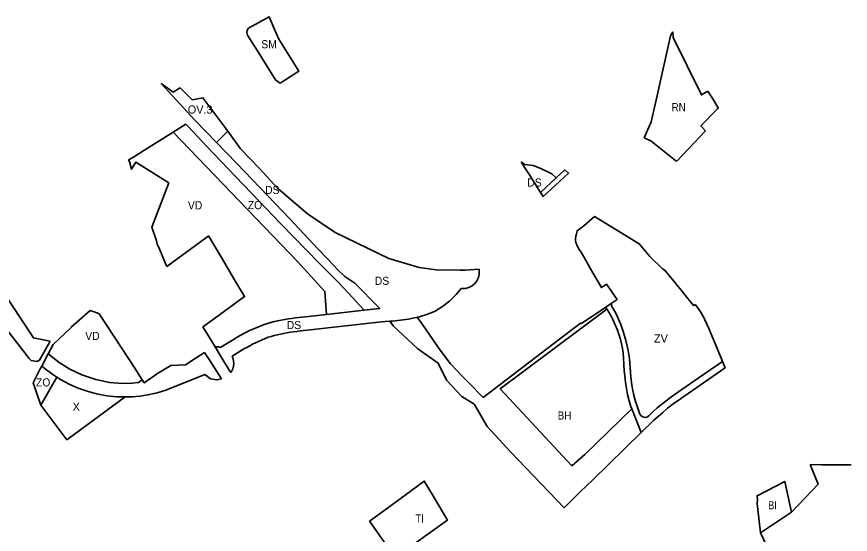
# Model space of a CAD drawing. Extents: x -650971 to -642489, y -1074311 to -1062745.
# Drawn here: x -647426 to -646196, y -1072507 to -1071744 of the extents above; entities that cross this region are included whole.
import ezdxf

# ---------------------------------------------------------------- set-up
doc = ezdxf.new("R2010")
doc.units = 0
doc.header["$LTSCALE"] = 4.8
for name, color, linetype, lineweight in [('1', 7, 'Continuous', 35), ('11', 7, 'Continuous', 35), ('15', 7, 'Continuous', 35), ('18', 7, 'Continuous', 35), ('2', 7, 'Continuous', 35), ('24', 7, 'Continuous', 35), ('30', 7, 'Continuous', 35), ('35', 7, 'Continuous', 35), ('40', 7, 'Continuous', 35), ('42', 7, 'Continuous', 35), ('48', 7, 'Continuous', 35), ('51', 7, 'Continuous', 35), ('62', 7, 'Continuous', 35), ('7', 7, 'Continuous', 35)]:
    doc.layers.add(name, color=color, linetype=linetype, lineweight=lineweight)

msp = doc.modelspace()

# ---------------------------------------------------------------- linework, layer by layer
at = {"layer": '1'}
for points in [[(-646549.793, -1072183.38), (-646554.56, -1072175.629), (-646555.051, -1072174.933), (-646712.634, -1072292.59), (-646606.848, -1072405.785)], [(-646518.208, -1072321.92), (-646587.666, -1072389.082), (-646606.848, -1072405.785), (-646712.634, -1072292.59), (-646555.051, -1072174.933)], [(-646555.051, -1072174.933), (-646554.56, -1072175.629), (-646549.793, -1072183.38), (-646546.09, -1072190.428), (-646542.484, -1072197.985), (-646539.168, -1072206.122), (-646536.772, -1072213.218), (-646535.344, -1072217.844), (-646533.286, -1072226.031), (-646531.93, -1072232.861), (-646530.892, -1072239.747), (-646530.188, -1072247.442), (-646529.182, -1072265.941), (-646528.566, -1072273.308), (-646527.5, -1072282.657), (-646526, -1072292.201), (-646524.282, -1072300.849), (-646522.007, -1072309.932), (-646519.417, -1072318.408), (-646518.208, -1072321.92)], [(-646539.168, -1072206.122), (-646542.484, -1072197.985), (-646546.09, -1072190.428), (-646549.793, -1072183.38)], [(-646529.182, -1072265.941), (-646530.188, -1072247.442), (-646530.892, -1072239.747), (-646531.93, -1072232.861), (-646533.286, -1072226.031), (-646535.344, -1072217.844), (-646536.772, -1072213.218), (-646539.168, -1072206.122)], [(-646518.208, -1072321.92), (-646519.417, -1072318.408), (-646522.007, -1072309.932), (-646524.282, -1072300.849), (-646526, -1072292.201), (-646527.5, -1072282.657), (-646528.566, -1072273.308), (-646529.182, -1072265.941)], [(-646606.848, -1072405.785), (-646587.666, -1072389.082), (-646518.208, -1072321.92)]]:
    msp.add_lwpolyline(points, dxfattribs=at)
at = {"layer": '11'}
for points in [[(-647212.66, -1071842.15), (-647205.62, -1071847.24), (-647194.96, -1071854.93), (-647185.62, -1071849.12), (-647184.81, -1071848.61)], [(-647131.146, -1071929.146), (-647163.08, -1071896.13), (-647212.66, -1071842.15)], [(-647184.81, -1071848.61), (-647167.15, -1071866.22), (-647151.07, -1071863.08), (-647118.79, -1071906.59), (-647114.479, -1071912.479), (-647131.146, -1071929.146)]]:
    msp.add_lwpolyline(points, dxfattribs=at)
at = {"layer": '15'}
msp.add_line((-646556.693, -1072172.159), (-646548.676, -1072166.737), dxfattribs=at)
for points in [[(-646652.864, -1072003.075), (-646629.655, -1071981.343), (-646617.21, -1071969.689), (-646611.438, -1071974.36), (-646624.385, -1071986.313)], [(-646624.385, -1071986.313), (-646631.409, -1071992.798), (-646649.112, -1072009.049), (-646652.864, -1072003.075)], [(-646518.208, -1072321.92), (-646519.417, -1072318.408), (-646522.007, -1072309.932), (-646524.282, -1072300.849), (-646526, -1072292.201), (-646527.5, -1072282.657), (-646528.566, -1072273.308), (-646529.182, -1072265.941), (-646530.188, -1072247.442), (-646530.892, -1072239.747), (-646531.93, -1072232.861), (-646533.286, -1072226.031), (-646535.344, -1072217.844), (-646536.772, -1072213.218), (-646539.168, -1072206.122), (-646542.484, -1072197.985), (-646546.09, -1072190.428), (-646549.793, -1072183.38), (-646554.56, -1072175.629), (-646555.051, -1072174.933), (-646556.693, -1072172.159)], [(-646548.676, -1072166.737), (-646547.606, -1072170.835), (-646541.822, -1072181.102), (-646534.527, -1072197.411), (-646530.167, -1072209.31), (-646526.798, -1072221.011), (-646523.628, -1072235.883), (-646521.646, -1072248.378), (-646519.756, -1072274.861), (-646518.079, -1072287.051), (-646516.692, -1072294.983), (-646515.305, -1072301.925), (-646512.729, -1072311.048), (-646509.954, -1072319.377), (-646506.189, -1072329.889), (-646504.802, -1072331.971), (-646503.018, -1072333.459), (-646500.244, -1072334.45), (-646497.569, -1072334.55), (-646494.794, -1072333.558), (-646492.813, -1072332.07), (-646486.273, -1072325.526), (-646480.923, -1072320.667), (-646462.79, -1072306.784), (-646455.557, -1072301.131), (-646420.085, -1072276.737), (-646384.056, -1072252.138), (-646380.12, -1072261.44)], [(-646380.12, -1072261.44), (-646459.03, -1072316.137), (-646465.227, -1072321.127), (-646473.069, -1072327.765), (-646485.656, -1072338.908), (-646504.244, -1072357.026), (-646518.208, -1072321.92)]]:
    msp.add_lwpolyline(points, dxfattribs=at)
at = {"layer": '18'}
for points in [[(-647037.23, -1071841.82), (-647040.2, -1071839.6), (-647044.12, -1071836.68), (-647073.19, -1071789.9), (-647074.99, -1071786.99), (-647085.25, -1071770.69), (-647086.19, -1071766.95), (-647085.71, -1071763.75), (-647084.95, -1071761.98), (-647083.97, -1071760.74), (-647053.43, -1071743.63), (-647044.83, -1071763.37)], [(-647044.83, -1071763.37), (-647039.14, -1071776.9), (-647009.514, -1071823.81), (-647037.23, -1071841.82)]]:
    msp.add_lwpolyline(points, dxfattribs=at)
at = {"layer": '2'}
msp.add_lwpolyline([(-646333.34, -1072461.67), (-646332.68, -1072456.19), (-646333.33, -1072450.12), (-646292.44, -1072428.89), (-646282.47, -1072474.34), (-646328.45, -1072504.81)], close=True, dxfattribs=at)
at = {"layer": '24'}
msp.add_line((-647389.072, -1072258.845), (-647379.422, -1072240.675), dxfattribs=at)
for points in [[(-646900.046, -1072175.154), (-646890.044, -1072174.056), (-646891.05, -1072172.79), (-646927.14, -1072136.74), (-646941.45, -1072126.84), (-646951.95, -1072116.84), (-646966.54, -1072101.4), (-646967.25, -1072100.6), (-646981.35, -1072085.77), (-647023.04, -1072041.63), (-647055.16, -1072007.74), (-647101.07, -1071960.24), (-647131.146, -1071929.146), (-647114.479, -1071912.479)], [(-647114.479, -1071912.479), (-647095.51, -1071938.39), (-647067.53, -1071967.54), (-647040.89, -1071996.58), (-646996.8, -1072034.35), (-646956.04, -1072061.95), (-646876.83, -1072100.12), (-646868.61, -1072102.6), (-646832.01, -1072113.66), (-646806.87, -1072116.94), (-646771.31, -1072117.49), (-646763.93, -1072117.61), (-646743.596, -1072115.986)], [(-646652.864, -1072003.075), (-646657.32, -1071995.98), (-646658.79, -1071993.62), (-646669.31, -1071976.77), (-646676.79, -1071964.97), (-646681.07, -1071958.16), (-646675.99, -1071961.64), (-646663.87, -1071963.26), (-646652.18, -1071967.73)], [(-646652.18, -1071967.73), (-646636.01, -1071975.35), (-646629.655, -1071981.343), (-646652.864, -1072003.075)], [(-646743.596, -1072115.986), (-646743.411, -1072123.612), (-646744.554, -1072128.415), (-646747.39, -1072134.069), (-646750.164, -1072137.467), (-646753.929, -1072140.612), (-646758.736, -1072143.137), (-646763.959, -1072144.535), (-646770.057, -1072144.677), (-646777.129, -1072153.576), (-646787.223, -1072163.402), (-646797.713, -1072171.151), (-646808.466, -1072177.78), (-646811.621, -1072179.254), (-646815.549, -1072180.906), (-646819.509, -1072182.408), (-646823.496, -1072183.769), (-646827.501, -1072184.997), (-646831.517, -1072186.103), (-646834.294, -1072186.789)], [(-647376.68, -1072222.29), (-647392.34, -1072250.02), (-647396.25, -1072252.14), (-647404.45, -1072250.66), (-647407.34, -1072247.93), (-647447.73, -1072195.72), (-647475.57, -1072159.74), (-647473.12, -1072157.91), (-647451.21, -1072142.08)], [(-647451.21, -1072142.08), (-647401.221, -1072217.342), (-647376.68, -1072222.29)], [(-647133, -1072230.754), (-647132.834, -1072230.735), (-647132.5, -1072230.7), (-647132.334, -1072230.684), (-647131.999, -1072230.656), (-647131.832, -1072230.644), (-647131.496, -1072230.623), (-647131.245, -1072230.61), (-647130.992, -1072230.599), (-647130.488, -1072230.587), (-647130.151, -1072230.584), (-647129.982, -1072230.584), (-647129.646, -1072230.588), (-647129.477, -1072230.592), (-647129.309, -1072230.597), (-647128.803, -1072230.619), (-647128.299, -1072230.653), (-647127.963, -1072230.679), (-647127.628, -1072230.711), (-647127.46, -1072230.729), (-647126.959, -1072230.789), (-647126.625, -1072230.835), (-647126.459, -1072230.86), (-647126.127, -1072230.912), (-647125.796, -1072230.97), (-647125.466, -1072231.031), (-647125.137, -1072231.097), (-647124.81, -1072231.168), (-647104.989, -1072219.005), (-647100.583, -1072216.405), (-647096.114, -1072213.845), (-647091.574, -1072211.346), (-647086.955, -1072208.921), (-647082.249, -1072206.591), (-647077.456, -1072204.373), (-647072.72, -1072202.352), (-647060.973, -1072197.439), (-647055.906, -1072195.893), (-647050.82, -1072194.5), (-647045.722, -1072193.245), (-647040.618, -1072192.117), (-647035.515, -1072191.104), (-647030.417, -1072190.192), (-647025.33, -1072189.37), (-647020.254, -1072188.623), (-647015.192, -1072187.939), (-647010.148, -1072187.308), (-647005.124, -1072186.715), (-647000.12, -1072186.148), (-646995.137, -1072185.597), (-646968.503, -1072182.672)], [(-646968.503, -1072182.672), (-646913.373, -1072176.618), (-646900.046, -1072175.154)], [(-646896.524, -1072194.888), (-646992.937, -1072205.475), (-646997.894, -1072206.024), (-647002.826, -1072206.583), (-647007.734, -1072207.162), (-647012.612, -1072207.773), (-647017.46, -1072208.427), (-647022.278, -1072209.136), (-647027.061, -1072209.91), (-647031.807, -1072210.758), (-647036.512, -1072211.693), (-647041.174, -1072212.723), (-647045.786, -1072213.858), (-647050.344, -1072215.107), (-647054.841, -1072216.479), (-647064.868, -1072220.746), (-647069.33, -1072222.651), (-647073.611, -1072224.631), (-647077.867, -1072226.739), (-647082.102, -1072228.962), (-647086.322, -1072231.285), (-647090.531, -1072233.695), (-647094.737, -1072236.177), (-647108.131, -1072244.373), (-647107.919, -1072244.822), (-647107.716, -1072245.278), (-647107.52, -1072245.74), (-647107.334, -1072246.209), (-647107.156, -1072246.683), (-647106.988, -1072247.163), (-647106.829, -1072247.649), (-647106.679, -1072248.139), (-647106.539, -1072248.635), (-647106.41, -1072249.135), (-647106.29, -1072249.64), (-647106.181, -1072250.148), (-647106.083, -1072250.66), (-647105.995, -1072251.176), (-647105.919, -1072251.695), (-647105.853, -1072252.216), (-647105.798, -1072252.739), (-647105.755, -1072253.265), (-647105.723, -1072253.792), (-647105.702, -1072254.321), (-647105.693, -1072254.85), (-647105.695, -1072255.38), (-647105.709, -1072255.91), (-647105.734, -1072256.44), (-647105.771, -1072256.969), (-647105.819, -1072257.497), (-647105.879, -1072258.024), (-647105.95, -1072258.549), (-647106.032, -1072259.072), (-647106.125, -1072259.592), (-647106.23, -1072260.11), (-647106.346, -1072260.624), (-647106.472, -1072261.135), (-647106.609, -1072261.643), (-647106.757, -1072262.146), (-647106.915, -1072262.644), (-647107.083, -1072263.138), (-647107.261, -1072263.626), (-647107.444, -1072264.097), (-647107.647, -1072264.587), (-647107.854, -1072265.058), (-647108.069, -1072265.524), (-647108.294, -1072265.983), (-647108.527, -1072266.435), (-647108.769, -1072266.88), (-647108.838, -1072267.002), (-647109.813, -1072268.588)], [(-646834.294, -1072186.789), (-646835.538, -1072187.097), (-646839.556, -1072187.988), (-646843.569, -1072188.789), (-646847.575, -1072189.507), (-646851.567, -1072190.155), (-646855.545, -1072190.741), (-646859.506, -1072191.276), (-646863.448, -1072191.771), (-646867.371, -1072192.234), (-646871.271, -1072192.675), (-646874.517, -1072192.471), (-646875.509, -1072192.58), (-646882.135, -1072193.308), (-646896.524, -1072194.888)], [(-647109.813, -1072268.588), (-647111.84, -1072265.38), (-647119.07, -1072253.56), (-647128.07, -1072238.83), (-647133, -1072230.754)], [(-647379.422, -1072240.675), (-647363.317, -1072253.632), (-647347.382, -1072263.623), (-647330.032, -1072271.935), (-647309.416, -1072278.875), (-647288.769, -1072283.003), (-647269.579, -1072284.489), (-647255.671, -1072284.192), (-647246.206, -1072283.328), (-647240.55, -1072279.42)], [(-647240.55, -1072279.42), (-647237.6, -1072283.78), (-647218.35, -1072269.67), (-647198.3, -1072258.09), (-647176.7, -1072257.24), (-647160.91, -1072246.82), (-647148.71, -1072238.76)], [(-647148.71, -1072238.76), (-647141.05, -1072250.54), (-647123.774, -1072277.899)], [(-647366.505, -1072275.41), (-647372.858, -1072271.363), (-647383.813, -1072263.219), (-647389.072, -1072258.845)], [(-647265.794, -1072304.439), (-647271.395, -1072304.452), (-647278.108, -1072304.147), (-647292.715, -1072302.646), (-647308.157, -1072299.786), (-647321.953, -1072296.073), (-647335.382, -1072291.341), (-647347.369, -1072286.111), (-647361.521, -1072278.584), (-647366.505, -1072275.41)], [(-647123.774, -1072277.899), (-647130.12, -1072279.44), (-647139.697, -1072277.484), (-647148.171, -1072271.47), (-647205.975, -1072294.599), (-647218.5, -1072298.335), (-647232.368, -1072301.4), (-647244.428, -1072303.192), (-647255.16, -1072304.123), (-647265.794, -1072304.439)]]:
    msp.add_lwpolyline(points, dxfattribs=at)
at = {"layer": '30'}
for points in [[(-646905.18, -1072487.8), (-646878.91, -1072468.54), (-646824.42, -1072428.58), (-646810.77, -1072451.09)], [(-646810.77, -1072451.09), (-646790.354, -1072486.136), (-646791.569, -1072487.198), (-646867.283, -1072540.984), (-646893.64, -1072504.45)], [(-646893.64, -1072504.45), (-646898.1, -1072498.02), (-646905.18, -1072487.8)]]:
    msp.add_lwpolyline(points, dxfattribs=at)
at = {"layer": '35'}
for points in [[(-647261.12, -1071954.82), (-647253.67, -1071950.76), (-647238.1, -1071941), (-647194.903, -1071913.941)], [(-647194.903, -1071913.941), (-647011.762, -1072104.502), (-646971.283, -1072148.82), (-646968.503, -1072182.672)], [(-647204.38, -1072111.87), (-647204.78, -1072110.92), (-647216.23, -1072084.14), (-647218.42, -1072079.01), (-647219.64, -1072074.29), (-647226.41, -1072054.11), (-647201.53, -1071988.71), (-647249.92, -1071958.12), (-647253.85, -1071964.38), (-647256.53, -1071968.64), (-647259.7, -1071957.06), (-647261.12, -1071954.82)], [(-647151.05, -1072201.21), (-647134.17, -1072188.95), (-647089.54, -1072156.53), (-647105.82, -1072129.3), (-647122.33, -1072101.34), (-647142.77, -1072067), (-647143.76, -1072067.69), (-647147.54, -1072070.29), (-647204.38, -1072111.87)], [(-647379.422, -1072240.675), (-647372.1, -1072226.89), (-647345.68, -1072201.82), (-647345.42, -1072201.58), (-647317.33, -1072176.99), (-647310.33, -1072179.58), (-647304.32, -1072181.81)], [(-647304.32, -1072181.81), (-647271.38, -1072232.23), (-647251.85, -1072262.12), (-647240.55, -1072279.42)], [(-646968.503, -1072182.672), (-646995.137, -1072185.597), (-647000.12, -1072186.148), (-647005.124, -1072186.715), (-647010.148, -1072187.308), (-647015.192, -1072187.939), (-647020.254, -1072188.623), (-647025.33, -1072189.37), (-647030.417, -1072190.192), (-647035.515, -1072191.104), (-647040.618, -1072192.117), (-647045.722, -1072193.245), (-647050.82, -1072194.5), (-647055.906, -1072195.893), (-647060.973, -1072197.439), (-647072.72, -1072202.352), (-647077.456, -1072204.373), (-647082.249, -1072206.591), (-647086.955, -1072208.921), (-647091.574, -1072211.346), (-647096.114, -1072213.845), (-647100.583, -1072216.405), (-647104.989, -1072219.005), (-647124.81, -1072231.168), (-647125.137, -1072231.097), (-647125.466, -1072231.031), (-647125.796, -1072230.97), (-647126.127, -1072230.912), (-647126.459, -1072230.86), (-647126.625, -1072230.835), (-647126.959, -1072230.789), (-647127.46, -1072230.729), (-647127.628, -1072230.711), (-647127.963, -1072230.679), (-647128.299, -1072230.653), (-647128.803, -1072230.619), (-647129.309, -1072230.597), (-647129.477, -1072230.592), (-647129.646, -1072230.588), (-647129.982, -1072230.584), (-647130.151, -1072230.584), (-647130.488, -1072230.587), (-647130.992, -1072230.599), (-647131.245, -1072230.61), (-647131.496, -1072230.623), (-647131.832, -1072230.644), (-647131.999, -1072230.656), (-647132.334, -1072230.684), (-647132.5, -1072230.7), (-647132.834, -1072230.735), (-647133, -1072230.754)], [(-647133, -1072230.754), (-647138.65, -1072221.5), (-647151.05, -1072201.21)], [(-647240.55, -1072279.42), (-647246.206, -1072283.328), (-647255.671, -1072284.192), (-647269.579, -1072284.489), (-647288.769, -1072283.003), (-647309.416, -1072278.875), (-647330.032, -1072271.935), (-647347.382, -1072263.623), (-647363.317, -1072253.632), (-647379.422, -1072240.675)]]:
    msp.add_lwpolyline(points, dxfattribs=at)
at = {"layer": '40'}
for points in [[(-646601, -1072067.55), (-646599.86, -1072063.71), (-646598.953, -1072059.791), (-646598.832, -1072059.247), (-646588.75, -1072052.06), (-646573.05, -1072038.46)], [(-646573.05, -1072038.46), (-646507.28, -1072078.4), (-646491.69, -1072097.45), (-646472.72, -1072115.38), (-646469.41, -1072117.44), (-646468.35, -1072118.76), (-646455.75, -1072134.29), (-646426.98, -1072169.74), (-646424.56, -1072167.96)], [(-646548.676, -1072166.737), (-646539.94, -1072160.83), (-646555.49, -1072138.17), (-646563.11, -1072143.03), (-646577.08, -1072118.7), (-646577.41, -1072117.76), (-646583.9, -1072106.42), (-646585.08, -1072104.81), (-646591.02, -1072094.4), (-646593.13, -1072091.01), (-646595.86, -1072086.82), (-646598.67, -1072081.55), (-646600.22, -1072077.86), (-646600.8, -1072075.94), (-646601.16, -1072074.07), (-646601.42, -1072071.01), (-646601, -1072067.55)], [(-646384.056, -1072252.138), (-646420.085, -1072276.737), (-646455.557, -1072301.131), (-646462.79, -1072306.784), (-646480.923, -1072320.667), (-646486.273, -1072325.526), (-646492.813, -1072332.07), (-646494.794, -1072333.558), (-646497.569, -1072334.55), (-646500.244, -1072334.45), (-646503.018, -1072333.459), (-646504.802, -1072331.971), (-646506.189, -1072329.889), (-646509.954, -1072319.377), (-646512.729, -1072311.048), (-646515.305, -1072301.925), (-646516.692, -1072294.983), (-646518.079, -1072287.051), (-646519.756, -1072274.861), (-646521.646, -1072248.378), (-646523.628, -1072235.883), (-646526.798, -1072221.011), (-646530.167, -1072209.31), (-646534.527, -1072197.411), (-646541.822, -1072181.102), (-646547.606, -1072170.835), (-646548.676, -1072166.737)], [(-646424.56, -1072167.96), (-646419.83, -1072174.51), (-646415.84, -1072180.43), (-646410.68, -1072189.36)], [(-646410.68, -1072189.36), (-646410.14, -1072190.49), (-646404.67, -1072203.42), (-646399.6, -1072215.39), (-646391.77, -1072233.91), (-646384.056, -1072252.138)]]:
    msp.add_lwpolyline(points, dxfattribs=at)
at = {"layer": '42'}
msp.add_line((-647194.903, -1071913.941), (-647176.32, -1071902.3), dxfattribs=at)
for points in [[(-646968.503, -1072182.672), (-646971.283, -1072148.82), (-647011.762, -1072104.502), (-647194.903, -1071913.941)], [(-647176.32, -1071902.3), (-647174.57, -1071904.06), (-647173.14, -1071905.45), (-647145.38, -1071935), (-647114.59, -1071967.77), (-647068.31, -1072015.68), (-647036.8, -1072048.41), (-646978.45, -1072108.09), (-646977.59, -1072108.96), (-646964.8, -1072121.83), (-646952.48, -1072134.22), (-646942.78, -1072144.74), (-646913.373, -1072176.618), (-646968.503, -1072182.672)], [(-646766.842, -1072275.063), (-646758.684, -1072283.41), (-646737.449, -1072305.019), (-646643.55, -1072233.5), (-646593.85, -1072195.48), (-646592.2, -1072196.17), (-646556.693, -1072172.159), (-646555.051, -1072174.933)], [(-646555.051, -1072174.933), (-646712.634, -1072292.59), (-646606.848, -1072405.785), (-646587.666, -1072389.082), (-646518.208, -1072321.92), (-646504.244, -1072357.026)], [(-646875.509, -1072192.58), (-646874.517, -1072192.471), (-646871.271, -1072192.675), (-646867.371, -1072192.234), (-646863.448, -1072191.771), (-646859.506, -1072191.276), (-646855.545, -1072190.741), (-646851.567, -1072190.155), (-646847.575, -1072189.507), (-646843.569, -1072188.789), (-646839.556, -1072187.988), (-646835.538, -1072187.097), (-646834.294, -1072186.789)], [(-646618.158, -1072468.098), (-646696.83, -1072385.81), (-646731.82, -1072348.2), (-646750.12, -1072315.82), (-646750.58, -1072315.02), (-646769.24, -1072303.65), (-646791.59, -1072279.78), (-646803.98, -1072254.74), (-646833.75, -1072233.32), (-646870.21, -1072199.51), (-646875.509, -1072192.58)], [(-646834.294, -1072186.789), (-646832.718, -1072189.697), (-646826.893, -1072197.582), (-646800.76, -1072235.668), (-646785.958, -1072255.505), (-646766.842, -1072275.063)], [(-647401.88, -1072283.4), (-647391.3, -1072263.04), (-647389.072, -1072258.845)], [(-647389.072, -1072258.845), (-647383.813, -1072263.219), (-647372.858, -1072271.363), (-647366.505, -1072275.41), (-647390.58, -1072316.75), (-647401.88, -1072283.4)], [(-646504.244, -1072357.026), (-646575.792, -1072426.789), (-646594.561, -1072444.38)], [(-646594.561, -1072444.38), (-646594.606, -1072444.422), (-646618.158, -1072468.098)]]:
    msp.add_lwpolyline(points, dxfattribs=at)
at = {"layer": '48'}
msp.add_line((-646328.45, -1072504.81), (-646282.47, -1072474.34), dxfattribs=at)
for points in [[(-646282.47, -1072474.34), (-646243.17, -1072432.88), (-646254.75, -1072404.25)], [(-646254.75, -1072404.25), (-646237.94, -1072404.35), (-646194.19, -1072404.62)], [(-646171.72, -1072803.51), (-646236.97, -1072678.31), (-646307.6, -1072547.74), (-646315.32, -1072532.01), (-646328.45, -1072504.81)]]:
    msp.add_lwpolyline(points, dxfattribs=at)
at = {"layer": '51'}
msp.add_line((-647390.58, -1072316.75), (-647366.505, -1072275.41), dxfattribs=at)
msp.add_lwpolyline([(-647366.505, -1072275.41), (-647361.521, -1072278.584), (-647347.369, -1072286.111), (-647335.382, -1072291.341), (-647321.953, -1072296.073), (-647308.157, -1072299.786), (-647292.715, -1072302.646), (-647278.108, -1072304.147), (-647271.395, -1072304.452), (-647265.794, -1072304.439), (-647351.86, -1072367.52), (-647390.58, -1072316.75)], dxfattribs=at)
at = {"layer": '7'}
for points in [[(-646499.741, -1071922.455), (-646489.34, -1071898.61), (-646481.02, -1071862.13), (-646461.09, -1071771.76), (-646457.52, -1071765.98)], [(-646457.52, -1071765.98), (-646456.96, -1071774.2), (-646415.46, -1071859.05), (-646405.99, -1071853.26)], [(-646405.99, -1071853.26), (-646399.72, -1071863.5), (-646390.732, -1071878.171), (-646391.83, -1071879.32)], [(-646391.83, -1071879.32), (-646416.2, -1071904.81), (-646409.4, -1071912.17), (-646426.18, -1071929.84), (-646451.87, -1071956.88)], [(-646451.87, -1071956.88), (-646453.04, -1071956.3), (-646490.111, -1071926.754), (-646499.741, -1071922.455)]]:
    msp.add_lwpolyline(points, dxfattribs=at)

# ---------------------------------------------------------------- texts
at = {"layer": '62'}
for s, width, p in [('SM', 0.95, (-647064.938, -1071790.245)), ('RN', 0.9, (-646459.448, -1071883.14)), ('DS', 0.95, (-646672.386, -1071994.148)), ('DS', 0.95, (-647059.386, -1072005.148)), ('VD', 0.95, (-647173.311, -1072027.838)), ('ZO', 0.95, (-647084.886, -1072027.486)), ('DS', 0.95, (-646897.386, -1072139.148)), ('DS', 0.95, (-647027.378, -1072204.379)), ('VD', 0.95, (-647324.74, -1072220.495)), ('ZO', 0.95, (-647397.457, -1072288.915)), ('BH', 0.9, (-646627.48, -1072337.818)), ('BI', 0.85, (-646317, -1072470.167)), ('TI', 0.85, (-646837.377, -1072489.619))]:
    msp.add_text(s, height=12, dxfattribs=dict(at, width=width)).set_placement(p)
for s, p in [('OV.3', (-647173.505, -1071886.6)), ('ZV', (-646485.386, -1072224.148)), ('X', (-647343.371, -1072324.801))]:
    msp.add_text(s, height=12, dxfattribs=at).set_placement(p)

doc.saveas('drawing.dxf')
